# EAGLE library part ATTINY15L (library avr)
MICROCONTROLLER 2.7 V 1 Kbytes FLASH 64 bytes EEPROM 4-channel 10 bit ADC
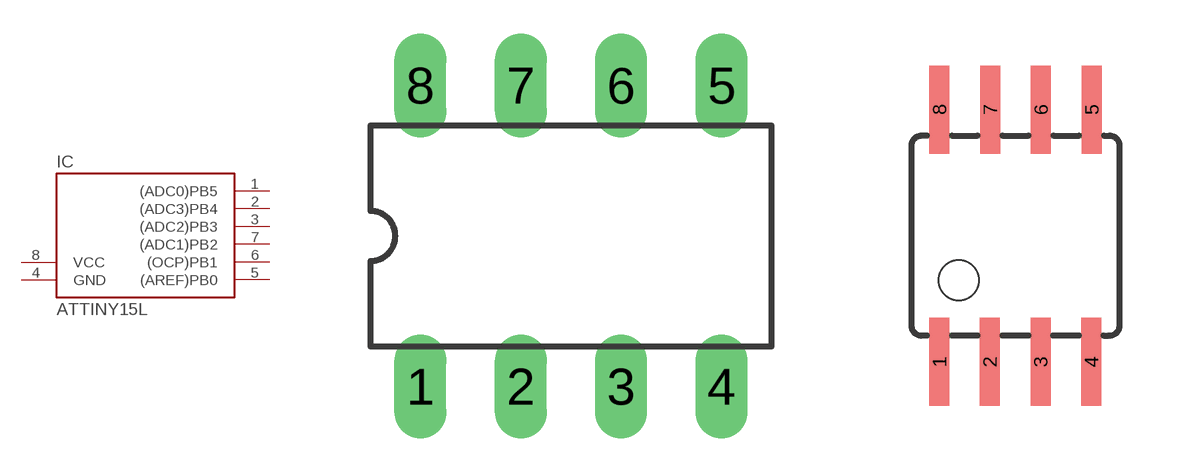
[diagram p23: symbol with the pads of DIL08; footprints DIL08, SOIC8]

Designator prefix IC

## ATTINY15L-1P  [DIL08]
1  (ADC0)PB5
2  (ADC3)PB4
3  (ADC2)PB3
4  GND  pwr
5  (AREF)PB0
6  (OCP)PB1
7  (ADC1)PB2
8  VCC  pwr

## ATTINY15L-1S  [SOIC8]
Pads as for DIL08

## Footprint DIL08 (pad centres in mm)
Dual In Line
drill 0.813 long: 1 -3.81,-3.81; 2 -1.27,-3.81; 3 1.27,-3.81; 4 3.81,-3.81; 5 3.81,3.81; 6 1.27,3.81; 7 -1.27,3.81; 8 -3.81,3.81

## Footprint SOIC8 (pad centres in mm)
Wide Plastic Gull Wing Small Outline Package
smd 0.5 x 2.2: 1 -1.905,-3.154; 2 -0.645,-3.154; 3 0.625,-3.154; 4 1.895,-3.154; 5 1.905,3.154; 6 0.635,3.154; 7 -0.635,3.154; 8 -1.905,3.154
